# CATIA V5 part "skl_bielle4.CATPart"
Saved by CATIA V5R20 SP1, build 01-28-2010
Part number: skl_bielle4
Publications: "Droite.1", "Droite.2", "Droite.3", "Plan xy"
Bounding box of the stored display mesh (mm): x 161.915 to 345.35, y 818.683 to 1128.443, z -100 to 0
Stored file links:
  C:\Users\Manon\Desktop\IAO\SKL_rlanglais\skl_bielle4.CATPart
  C:\Users\Manon\Desktop\IAO\SKL_rlanglais\SKL_rlanglais.CATProduct
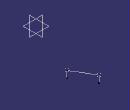
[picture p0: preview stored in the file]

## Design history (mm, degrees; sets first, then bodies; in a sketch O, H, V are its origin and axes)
Set1
  Point1 "E": linked copy from another document
  Point2 "F": linked copy from another document
Set2
  Line1: type PtPt, FirstPoint Point1, SecondPoint Point2
  Line2: type Normal, RefPoint Point1, RefSkin xy-plane, Start 0, End 100
  Line3: type Normal, RefPoint Point2, RefSkin xy-plane, Start 0, End 100
Body1 (main body)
